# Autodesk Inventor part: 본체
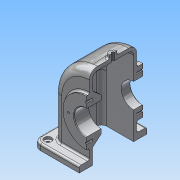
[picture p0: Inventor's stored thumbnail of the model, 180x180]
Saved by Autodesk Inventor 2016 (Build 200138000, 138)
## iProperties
Created: 2018-08
Part Number: 본체
Material: 알루미늄 6061
Document SubType Name: Modeling
Designer: Administrator
Density: 2.7 g/cm^3
Appearance: 알루미늄 - 평지
Mass: 1092.08 g
Surface Area: 1182.21 cm^2
Volume: 404.475 cm^3
Author: Administrator
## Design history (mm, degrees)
sketch "스케치1"
  geometry: L1 (-75, 55)-(75, 55); L2 (75, 55)-(75, -55); L3 (75, -55)-(-75, -55); L4 (-75, -55)-(-75, 55); L5 (-75, 55)-(75, -55); L6 (75, 55)-(-75, -55); 1 further point
  constraints: 12 end point, 2 midpoint, 2 parallel, 1 horizontal, 1 perpendicular
  dimensions: "d0" = 150 distance of L2.end L3.end; "d1" = 110 distance of L1.end L2.end
extrude "돌출1" new body sketch "스케치1" distance "d2" = 10; taper "d3" = 0 deg
sketch "스케치2"
  geometry: L1 (-75, 10)-(75, 10) reference; L2 (58, 10)-(-58, 10); L3 (-58, 10)-(-58, 78); L4 (-58, 78)-(58, 78); L5 (58, 78)-(58, 10); A1 r 58 centre (0, 78) between (58, 78) and (-58, 78); 1 further point
  constraints: 8 end point, 2 parallel, 2 point on circle, 1 centre point, 1 horizontal, 1 midpoint, 1 perpendicular, 1 point on line
  dimensions: "d4" = 68 distance of L4.end L2.start; "d5" = 116 distance of L3.end L4.end; "d6" = 58 distance from line of point (0, 0) L5
extrude "돌출2" join sketch "스케치2" stored distance "d7" = 77; taper "d8" = 0 deg
sketch "스케치3"
  geometry: L1 (58, 10)-(58, 78) reference; L2 (-58, 78)-(-58, 10) reference; L3 (58, 10)-(-58, 10) reference; L4 (52, 78)-(52, 0); L5 (52, 0)-(-52, 0); L6 (-52, 0)-(-52, 78); L7 (75, 0)-(-75, 0) reference; A1 r 58 centre (0, 78) between (58, 78) and (-58, 78) reference; A2 r 52 centre (0, 78) between (52, 78) and (-52, 78); 1 further point
  constraints: 6 end point, 2 point on circle, 1 centre point, 1 collinear, 1 midpoint, 1 vertical, 1 other
  dimensions: "d9" = 6 radial gap between concentric circles of A1 A2; "d10" = 52 distance from line of point (0, 0) L6
extrude "돌출3" cut sketch "스케치3" stored distance "d11" = 67; taper "d12" = 0 deg
sketch "스케치5"
  geometry: L1 (-71.953, 65)-(86.967, 65); L2 (38.5, 10)-(38.5, 78) reference; L3 (38.5, 27)-(48.5, 27); L4 (48.5, 27)-(48.5, 65); L5 (48.5, 65)-(38.5, 65); L6 (38.5, 65)-(38.5, 27); 1 further point
  constraints: 10 end point, 2 horizontal, 2 parallel, 2 point on line, 1 perpendicular
  dimensions: "d19" = 65 distance from line of point (0, 0) L1; "d20" = 76 diameter of L3 L1; "d21" = 10 distance of L3.start L3.end
revolve "회전2" sketch "스케치5" stored, may be unused: angle "d22" = 90 deg
node "작업 평면1"
sketch "스케치6"
  geometry: L1 (-58, -38.5)-(58, -38.5) reference; L2 (-58, 38.5)-(-58, -38.5) reference; C1 r 6 at (0, 0); 1 further point
  constraints: 1 centre point
  dimensions: "d33" = 12 diameter of C1; "d34" = 38.5 distance from line of L1 C1.centre; "d35" = 58 distance from line of L2 C1.centre
extrude "돌출4" join sketch "스케치6" stored distance "d36" = 67; taper "d37" = 5 deg
hole "구멍2" diameter "d40" = 4.459; stored, may be unused: countersink angle "d44" = 90 deg, drill point angle "d46" = 0 deg; dims "d38" = 10, "d39" = 10, "d41" = 10, "d42" = 4, "d43" = 2, "d45" = 12.8
sketch "스케치8"
  geometry: L1 (0, 0)-(0, -29); C1 r 20 at (0, 0) reference; C2 r 1.621 at (0, -29) reference; 2 further points
  constraints: 2 end point, 1 coincident, 1 vertical
  dimensions: "d58" = 29 distance of L1.start L1.end (derived)
hole "구멍4" sketch "스케치8" at (0, -29) diameter "d59" = 3.242; stored, may be unused: countersink angle "d63" = 90 deg, drill point angle "d65" = 118 deg; dims "d60" = 8, "d61" = 4, "d62" = 2, "d64" = 10
sketch "스케치9"
  geometry: L1 (0, 0)-(-68, 0) reference; L2 (10, 93.5)-(10, -16.5) reference; 2 further points
  constraints: 1 other
  dimensions: "d69" = 38.5 distance from line of L1 point (-30, 38.5); "d70" = 40 distance from line of L2 point (-30, 38.5)
feature "엠보싱1" sketch "스케치9" dims "d0" = 150, "d1" = 110, "d71" = 0.5, "d72" = 0
sketch "스케치10"
  geometry: L1 (75, -55)-(-75, -55) reference; L2 (-75, -55)-(-75, 55) reference; 2 further points
  dimensions: "d73" = 12 distance from line of L1 point (-63, -43); "d74" = 12 distance from line of L2 point (-63, -43)
hole "구멍5" sketch "스케치10" at (-63, -43) diameter "d75" = 5; stored, may be unused: countersink angle "d79" = 90 deg, drill point angle "d81" = 118 deg; dims "d76" = 6, "d77" = 12, "d78" = 4, "d80" = 8
fillet "모깎기1" dims "d88" = 13
fillet "모깎기2" dims "d89" = 12
fillet "모깎기3" dims "d90" = 3
fillet "모깎기4" dims "d91" = 8
fillet "모깎기6" dims "d96" = 3
sketch "스케치11"
  geometry: L1 (-82.499, 65)-(165.737, 65); L2 (-19.5, 65)-(-19.5, 93); L3 (-19.5, 93)-(-33.5, 104.747); L4 (-33.5, 104.747)-(-33.5, 65); L5 (-33.5, 78)-(-33.5, 0) reference; L6 (-19.5, 65)-(-33.5, 65); L7 (-33.5, 122)-(-33.5, 78) reference; 1 further point
  constraints: 10 end point, 4 point on line, 1 horizontal, 1 perpendicular, 1 vertical
  dimensions: "d98" = 65 distance from line of point (0, 0) L1; "d99" = 56 diameter of L2.end L1; "d100" = 50 deg angle of L3 L2; "d101" = 14 distance between parallel lines of L2 L4
revolve "회전3" sketch "스케치11" stored, may be unused: angle "d102" = 90 deg
sketch "스케치12"
  geometry: L1 (-64.819, 65)-(64.376, 65); L2 (-38.5, 13)-(-38.5, 78) reference; L3 (-38.5, 65)-(-43.5, 65); L4 (-43.5, 65)-(-43.5, 103); L5 (-43.5, 103)-(-38.5, 103); L6 (-38.5, 103)-(-38.5, 65); 1 further point
  constraints: 10 end point, 2 horizontal, 2 parallel, 2 point on line, 1 perpendicular
  dimensions: "d103" = 65 distance from line of point (0, 0) L1; "d104" = 5 distance of L4.end L5.end; "d105" = 76 diameter of L5 L1
revolve "회전4" sketch "스케치12" stored, may be unused: angle "d106" = 90 deg
hole "구멍6" diameter "d109" = 40; stored, may be unused: countersink angle "d113" = 90 deg, drill point angle "d115" = 118 deg; dims "d107" = 10, "d108" = 10, "d110" = 6, "d111" = 12, "d112" = 4, "d114" = 8
fillet "모깎기8" dims "d116" = 3
fillet "모깎기9" dims "d117" = 3
chamfer "모따기2" distance "d118" = 1; stored, may be unused: second distance "d119" = 2, angle "d120" = 45 deg
sketch "스케치13"
  geometry: L1 (0, 0)-(0, 29); C1 r 20 at (0, 0) reference; C2 r 1.621 at (0, 29) reference; 2 further points
  constraints: 2 end point, 1 coincident, 1 vertical
  dimensions: "d121" = 29 distance of L1.start L1.end (derived)
hole "구멍7" sketch "스케치13" at (0, 29) diameter "d122" = 3.242; stored, may be unused: countersink angle "d126" = 90 deg, drill point angle "d128" = 118 deg; dims "d123" = 8, "d124" = 12, "d125" = 4, "d127" = 10
sketch "스케치14"
  geometry: L1 (-105.188, 174.643)-(87.768, 174.643); L2 (87.768, 174.643)-(87.768, -22.333); L3 (87.768, -22.333)-(-105.188, -22.333); L4 (-105.188, -22.333)-(-105.188, 174.643); 1 further point
  constraints: 8 end point, 2 parallel, 1 horizontal, 1 perpendicular
extrude "돌출5" cut sketch "스케치14" stored distance "d132" = 10; taper "d133" = 0 deg
node "솔리드1"
pattern_circular "원형 패턴2" dims angle "d67" = 360 deg
pattern_linear "직사각형 패턴1" dims "d84" = 126, "d87" = 86
pattern_circular "원형 패턴3" dims angle "d130" = 360 deg
other parameters: "d32" = 142
